// Mitsubishi GX Works2 project: 43.5台电机顺起顺停   PLC: FX3U/FX3UC

PROGRAM MAIN
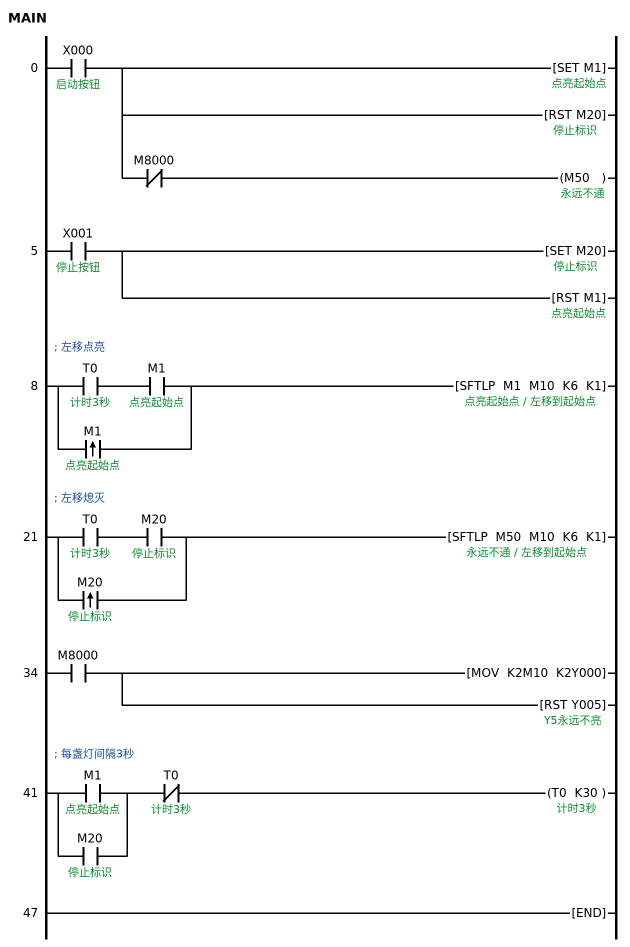
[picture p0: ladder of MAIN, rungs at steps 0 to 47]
0     LD      X000  ; 启动按钮
      SET     M1  ; 点亮起始点
      RST     M20  ; 停止标识
      ANI     M8000
      OUT     M50  ; 永远不通
5     LD      X001  ; 停止按钮
      SET     M20  ; 停止标识
      RST     M1  ; 点亮起始点
; 左移点亮
8     LD      T0  ; 计时3秒
      AND     M1  ; 点亮起始点
      ORP     M1  ; 点亮起始点
      SFTLP   M1 M10 K6 K1  ; 左移到起始点
        [note] 把1左移
; 左移熄灭
21    LD      T0  ; 计时3秒
      AND     M20  ; 停止标识
      ORP     M20  ; 停止标识
      SFTLP   M50 M10 K6 K1
        [note] 把0左移
34    LD      M8000
      MOV     K2M10 K2Y000
      RST     Y005  ; Y5永远不亮
; 每盏灯间隔3秒
41    LD      M1  ; 点亮起始点
      OR      M20  ; 停止标识
      ANI     T0  ; 计时3秒
      OUT     T0 K30  ; 计时3秒
47    END
END_PROGRAM
